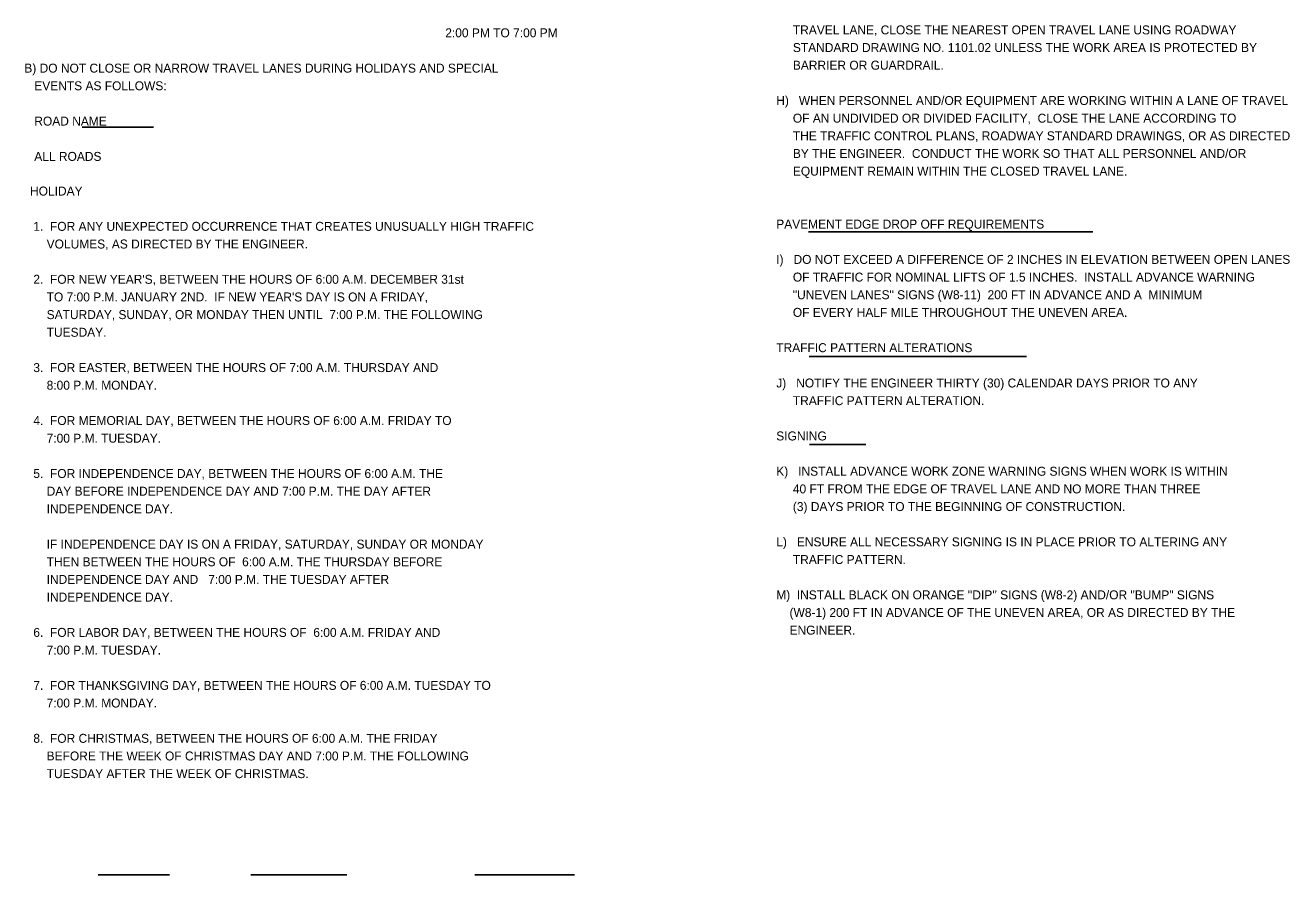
# Model space of a CAD drawing. Extents: x 762655 to 770567, y 650864 to 655190.
# Drawn here: x 765707 to 766554, y 651272 to 651842 of the extents above; entities that cross this region are included whole.
import ezdxf

# ---------------------------------------------------------------- set-up
doc = ezdxf.new("R2010")
doc.units = 0
doc.layers.add('Default', color=7, linetype='Continuous')

msp = doc.modelspace()

# ---------------------------------------------------------------- linework, layer by layer
at = {"layer": 'Default'}
for p, q in [((765744.72, 651773.57), (765792.59, 651773.57)), ((766231.83, 651703.28), (766422.3, 651703.28)), ((766232.13, 651619.84), (766377.86, 651619.84)), ((766232.47, 651560.86), (766270.2, 651560.86)), ((765755.59, 651272.48), (765803.33, 651272.48)), ((765857.94, 651272.48), (765922.12, 651272.48)), ((766008.04, 651272.48), (766074.81, 651272.48))]:
    msp.add_line(p, q, dxfattribs=at)

# ---------------------------------------------------------------- texts
for s, p in [('        2:00 PM TO 7:00 PM', (765970.36, 651833.78)), ('            TRAVEL LANE, CLOSE THE NEAREST OPEN TRAVEL LANE USING ROADWAY ', (766194.49, 651835.73)), ('            STANDARD DRAWING NO. 1101.02 UNLESS THE WORK AREA IS PROTECTED BY ', (766194.49, 651823.9)), ('       B) DO NOT CLOSE OR NARROW TRAVEL LANES DURING HOLIDAYS AND SPECIAL', (765690.36, 651810.11)), ('            BARRIER OR GUARDRAIL.', (766194.49, 651812.06)), ('          EVENTS AS FOLLOWS:', (765690.36, 651798.28)), ('       H)   WHEN PERSONNEL AND/OR EQUIPMENT ARE WORKING WITHIN A LANE OF TRAVEL', (766194.49, 651788.4)), ('          ROAD NAME ', (765690.36, 651774.61)), ('            OF AN UNDIVIDED OR DIVIDED FACILITY,  CLOSE THE LANE ACCORDING TO', (766194.49, 651776.56)), ('            THE TRAFFIC CONTROL PLANS, ROADWAY STANDARD DRAWINGS, OR AS DIRECTED', (766194.49, 651764.73)), ('          ALL ROADS ', (765690.36, 651750.94)), ('            BY THE ENGINEER.  CONDUCT THE WORK SO THAT ALL PERSONNEL AND/OR ', (766194.49, 651752.9)), ('            EQUIPMENT REMAIN WITHIN THE CLOSED TRAVEL LANE.', (766194.49, 651741.06)), ('           HOLIDAY', (765685.27, 651727.72)), ('            1.  FOR ANY UNEXPECTED OCCURRENCE THAT CREATES UNUSUALLY HIGH TRAFFIC ', (765685.27, 651704.06)), ('       PAVEMENT EDGE DROP OFF REQUIREMENTS', (766194.49, 651705.56)), ('                VOLUMES, AS DIRECTED BY THE ENGINEER.', (765685.27, 651692.22)), ('       I)   DO NOT EXCEED A DIFFERENCE OF 2 INCHES IN ELEVATION BETWEEN OPEN LANES', (766194.49, 651681.9)), ('            OF TRAFFIC FOR NOMINAL LIFTS OF 1.5 INCHES.  INSTALL ADVANCE WARNING', (766194.49, 651670.06)), ("            2.  FOR NEW YEAR'S, BETWEEN THE HOURS OF 6:00 A.M. DECEMBER 31st", (765685.27, 651668.56)), ("                TO 7:00 P.M. JANUARY 2ND.  IF NEW YEAR'S DAY IS ON A FRIDAY,", (765685.27, 651656.72)), ('            "UNEVEN LANES" SIGNS (W8-11)  200 FT IN ADVANCE AND A  MINIMUM ', (766194.49, 651658.23)), ('                SATURDAY, SUNDAY, OR MONDAY THEN UNTIL  7:00 P.M. THE FOLLOWING ', (765685.27, 651644.89)), ('            OF EVERY HALF MILE THROUGHOUT THE UNEVEN AREA.', (766194.49, 651646.4)), ('                TUESDAY.  ', (765685.27, 651633.06)), ('       TRAFFIC PATTERN ALTERATIONS', (766194.49, 651622.73)), ('            3.  FOR EASTER, BETWEEN THE HOURS OF 7:00 A.M. THURSDAY AND', (765685.27, 651609.39)), ('                8:00 P.M. MONDAY.', (765685.27, 651597.56)), ('       J)   NOTIFY THE ENGINEER THIRTY (30) CALENDAR DAYS PRIOR TO ANY', (766194.49, 651599.06)), ('            TRAFFIC PATTERN ALTERATION.', (766194.49, 651587.23)), ('            4.  FOR MEMORIAL DAY, BETWEEN THE HOURS OF 6:00 A.M. FRIDAY TO', (765685.27, 651573.89)), ('                7:00 P.M. TUESDAY.', (765685.27, 651562.06)), ('       SIGNING', (766194.49, 651563.56)), ('            5.  FOR INDEPENDENCE DAY, BETWEEN THE HOURS OF 6:00 A.M. THE', (765685.27, 651538.39)), ('       K)   INSTALL ADVANCE WORK ZONE WARNING SIGNS WHEN WORK IS WITHIN ', (766194.49, 651539.9)), ('                DAY BEFORE INDEPENDENCE DAY AND 7:00 P.M. THE DAY AFTER', (765685.27, 651526.56)), ('            40 FT FROM THE EDGE OF TRAVEL LANE AND NO MORE THAN THREE', (766194.49, 651528.06)), ('                INDEPENDENCE DAY.', (765685.27, 651514.72)), ('            (3) DAYS PRIOR TO THE BEGINNING OF CONSTRUCTION.', (766194.49, 651516.23)), ('       L)   ENSURE ALL NECESSARY SIGNING IS IN PLACE PRIOR TO ALTERING ANY', (766194.49, 651492.56)), ('                IF INDEPENDENCE DAY IS ON A FRIDAY, SATURDAY, SUNDAY OR MONDAY  ', (765685.27, 651491.06)), ('                THEN BETWEEN THE HOURS OF  6:00 A.M. THE THURSDAY BEFORE ', (765685.27, 651479.22)), ('            TRAFFIC PATTERN.', (766194.49, 651480.73)), ('                INDEPENDENCE DAY AND   7:00 P.M. THE TUESDAY AFTER', (765685.27, 651467.39)), ('                INDEPENDENCE DAY.   ', (765685.27, 651455.56)), ('       M)  INSTALL BLACK ON ORANGE \'\'DIP\'\' SIGNS (W8-2) AND/OR "BUMP" SIGNS  ', (766194.49, 651457.06)), ('           (W8-1) 200 FT IN ADVANCE OF THE UNEVEN AREA, OR AS DIRECTED BY THE ', (766194.49, 651445.23)), ('           ENGINEER. ', (766194.49, 651433.4)), ('            6.  FOR LABOR DAY, BETWEEN THE HOURS OF  6:00 A.M. FRIDAY AND', (765685.27, 651431.89)), ('                7:00 P.M. TUESDAY.', (765685.27, 651420.06)), ('            7.  FOR THANKSGIVING DAY, BETWEEN THE HOURS OF 6:00 A.M. TUESDAY TO', (765685.27, 651396.39)), ('                7:00 P.M. MONDAY.', (765685.27, 651384.56)), ('            8.  FOR CHRISTMAS, BETWEEN THE HOURS OF 6:00 A.M. THE FRIDAY', (765685.27, 651360.89)), ('                BEFORE THE WEEK OF CHRISTMAS DAY AND 7:00 P.M. THE FOLLOWING', (765685.27, 651349.06)), ('                TUESDAY AFTER THE WEEK OF CHRISTMAS.', (765685.27, 651337.22))]:
    msp.add_text(s, height=6, dxfattribs=at).set_placement(p)

doc.saveas('drawing.dxf')
